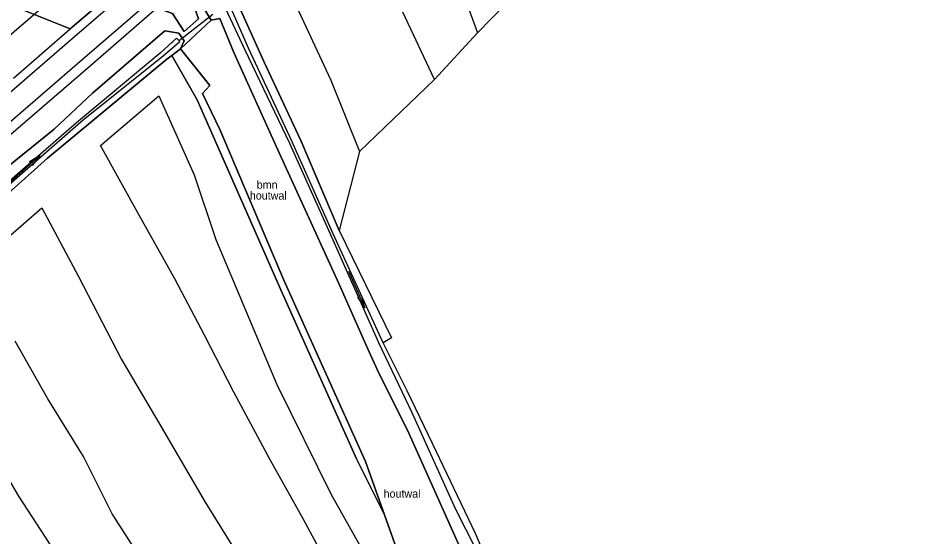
# Model space of a CAD drawing. Extents: x 154825 to 158680, y 370717 to 378075.
# Drawn here: x 156377.5 to 156491.8, y 376409.5 to 376474.3 of the extents above; entities that cross this region are included whole.
import ezdxf

# ---------------------------------------------------------------- set-up
doc = ezdxf.new("R2010")
doc.units = 0
for name, color, linetype in [('boomgroep(vs)', 7, 'Continuous'), ('cultuurscheiding', 7, 'Continuous'), ('deelstreep(1-1)', 7, 'Continuous'), ('duiker lijn', 7, 'Continuous'), ('hoogteverschillijn', 7, 'Continuous'), ('houtwal(vs)', 7, 'Continuous'), ('insteek sloot', 7, 'Continuous'), ('maaiveldlijn algemeen - gesloten verharding', 7, 'Continuous'), ('maaiveldlijn algemeen - open verharding', 7, 'Continuous'), ('Sloot bodem', 7, 'Continuous'), ('stroomrichting  watergangen', 7, 'Continuous'), ('talud(boven)', 7, 'Continuous'), ('talud(onder)', 7, 'Continuous'), ('vlak_Grasland', 7, 'Continuous'), ('vlak_Grazige_vegetatie', 7, 'Continuous'), ('vlak_Houtwal', 7, 'Continuous')]:
    doc.layers.add(name, color=color, linetype=linetype)

msp = doc.modelspace()

# ---------------------------------------------------------------- linework, layer by layer
at = {"layer": 'cultuurscheiding'}
for points in [[(156397.71, 376470.44), (156401.53, 376474)], [(156452.65, 376347.26), (156446.7, 376358.65), (156445.4, 376361.14), (156438.16, 376376.92), (156432.48, 376390.3), (156425.59, 376405.55), (156423.21, 376412.21), (156420.83, 376418.88)]]:
    msp.add_lwpolyline(points, dxfattribs=at)
at = {"layer": 'deelstreep(1-1)'}
for points in [[(156516.83, 376582.62), (156511, 376577.54), (156493.7, 376562.56), (156474.6, 376546.08), (156453.2, 376527.6), (156434.78, 376511.75), (156416.83, 376496.18), (156407.99, 376488.58), (156398.63, 376480.48), (156385.72, 376469.31), (156365.99, 376452.26), (156341.76, 376431.35), (156332.22, 376423.09), (156319.31, 376411.94), (156302.65, 376397.56), (156288.29, 376385.16), (156270.13, 376369.48), (156252.69, 376354.41), (156230.71, 376335.36), (156215.59, 376322.29), (156199.58, 376308.45), (156183.79, 376294.7), (156174.04, 376286.04)], [(156396.64, 376482.44), (156384.5, 376471.95), (156365.43, 376455.45), (156339.64, 376433.19), (156325.08, 376420.64), (156318.27, 376414.74), (156309.76, 376407.44), (156295.49, 376395.09), (156278.82, 376380.65), (156257.66, 376362.34), (156244, 376350.5), (156228.74, 376337.37), (156210.53, 376321.66), (156193.88, 376307.21), (156180.98, 376295.95), (156172.67, 376288.57)]]:
    msp.add_lwpolyline(points, dxfattribs=at)
at = {"layer": 'duiker lijn'}
for points in [[(156381.13, 376476.15), (156374.83, 376470.77)], [(156401.75, 376474.73), (156397.61, 376471.49)]]:
    msp.add_lwpolyline(points, dxfattribs=at)
at = {"layer": 'hoogteverschillijn'}
for points in [[(156430.99, 376482.94), (156434.81, 376472.42), (156441.98, 376479.81)], [(156411.65, 376476.95), (156416.51, 376466.53), (156420.08, 376457.59), (156429.44, 376466.61), (156425.47, 376475.01)], [(156418.27, 376401.97), (156413.05, 376411.71), (156408.9, 376419.06), (156404.37, 376427.51), (156400.72, 376434.67), (156397, 376441.68), (156392.62, 376449.57), (156387.71, 376458.36), (156395.02, 376464.55), (156399.43, 376454.71), (156402.15, 376446.59), (156406.21, 376436.92), (156409.74, 376428.48), (156416.52, 376414.76), (156421.96, 376405.11)], [(156371.57, 376442.92), (156380.41, 376450.57), (156384.97, 376441.97), (156390.35, 376431.63), (156395.02, 376423.71), (156400.82, 376413.77), (156406.72, 376404.24)], [(156393.38, 376405.8), (156389.17, 376412.33), (156385.61, 376419.48), (156381.16, 376426.69), (156377.09, 376433.91)], [(156372.83, 376422.46), (156377.47, 376414.52), (156382.98, 376406.08)]]:
    msp.add_lwpolyline(points, dxfattribs=at)
at = {"layer": 'insteek sloot'}
for points in [[(156401.53, 376474), (156400.68, 376475.44), (156400.56, 376476.25), (156404.61, 376480.44), (156405.83, 376481.53), (156416.42, 376490.67), (156424.67, 376497.23), (156425.57, 376496.46), (156426.08, 376495.82), (156425.87, 376495.16)], [(156415.57, 376486.13), (156408.41, 376479.61), (156404.91, 376475.98), (156408.18, 376468.77), (156412.75, 376458.97), (156417.53, 376447.73), (156424.07, 376434.34)], [(156401.53, 376474), (156402.63, 376474.21), (156404.38, 376469.98), (156409.85, 376457.89), (156417.48, 376441.12), (156420.88, 376433.49), (156422.33, 376430.29), (156426.23, 376422.42), (156433.21, 376406.88)], [(156397.71, 376470.44), (156398.16, 376471.43), (156397.51, 376472.38), (156395.76, 376472.68), (156386.74, 376464.91), (156381.96, 376460.41), (156372.31, 376452.63), (156362.32, 376443.31), (156361.14, 376441.74), (156361.34, 376441.19), (156362.08, 376440.64)], [(156362.08, 376440.64), (156363, 376440.98), (156374.21, 376450.62), (156381.12, 376456.78), (156396.01, 376469.15), (156396.64, 376469.62), (156397.71, 376470.44)]]:
    msp.add_lwpolyline(points, dxfattribs=at)
at = {"layer": 'maaiveldlijn algemeen - gesloten verharding'}
for points in [[(156383.95, 376472.95), (156396.18, 376483.38), (156405.38, 376491.44)], [(156237.38, 376339.6), (156253.19, 376353.26), (156271.08, 376368.68), (156289.08, 376384.27), (156303.76, 376396.95), (156320.09, 376411.16), (156332.73, 376421.99), (156342.37, 376430.35), (156366.77, 376451.41), (156386.5, 376468.35), (156394.77, 376475.56), (156398.53, 376478.84)], [(156376.85, 376466.78), (156383.95, 376472.95)]]:
    msp.add_lwpolyline(points, dxfattribs=at)
at = {"layer": 'maaiveldlijn algemeen - open verharding'}
for points in [[(156364.32, 376490.52), (156378.11, 376475.29), (156383.95, 376472.95)], [(156398.53, 376478.84), (156398.91, 376477.17), (156399.97, 376474.2), (156398.17, 376472.6), (156396.74, 376474.87), (156394.77, 376475.56)]]:
    msp.add_lwpolyline(points, dxfattribs=at)
at = {"layer": 'Sloot bodem'}
for points in [[(156436.48, 376405.4), (156434.58, 376409.86), (156429.21, 376421.11), (156426.03, 376427.69), (156423.04, 376433.69), (156416.76, 376447.38), (156411.65, 376458.81), (156406.23, 376470.52), (156403.75, 376476.15)], [(156403.28, 376475.55), (156405.75, 376470.3), (156411.34, 376458.66), (156416.4, 376447.3), (156422.43, 376433.73), (156426.61, 376425), (156432.08, 376412.91), (156435.99, 376405.22)], [(156397.63, 376471.34), (156397.22, 376471.79), (156395.22, 376469.92), (156384.72, 376461.21), (156373.14, 376451.17), (156365.95, 376444.97), (156361.92, 376441.45), (156362.33, 376441.17), (156366.29, 376444.83), (156373.33, 376450.92), (156385.59, 376461.59), (156395.56, 376469.56), (156397.63, 376471.34)]]:
    msp.add_lwpolyline(points, dxfattribs=at)
at = {"layer": 'stroomrichting  watergangen'}
for p, q in [((156376.46, 376453.76), (156380.17, 376457.1)), ((156380.15, 376457.1), (156378.81, 376456.26)), ((156380.17, 376457.1), (156379.2, 376455.86)), ((156418.71, 376442.64), (156420.75, 376438.08)), ((156420.75, 376438.08), (156419.87, 376439.39)), ((156420.76, 376438.1), (156420.37, 376439.63))]:
    msp.add_line(p, q, dxfattribs=at)
at = {"layer": 'talud(boven)'}
msp.add_lwpolyline([(156420.83, 376418.88), (156410.61, 376441.54), (156402.68, 376460.28), (156400.46, 376464.86), (156401.4, 376465.86), (156397.71, 376470.44)], dxfattribs=at)
at = {"layer": 'talud(onder)'}
msp.add_lwpolyline([(156396.64, 376469.62), (156399.82, 376464.08), (156410.25, 376440.3), (156419.69, 376419.2), (156423.21, 376412.21)], dxfattribs=at)
at = {"layer": 'vlak_Grasland'}
for points in [[(156498.8, 376534.69), (156491.35, 376527.99), (156483.75, 376520.44), (156476.1, 376513.3), (156463.92, 376501.56), (156456.32, 376494.05), (156449.89, 376487.84), (156441.98, 376479.81), (156434.81, 376472.42), (156429.44, 376466.61), (156420.08, 376457.59), (156417.53, 376447.73), (156412.75, 376458.97), (156408.18, 376468.77), (156404.91, 376475.98), (156408.41, 376479.61), (156415.57, 376486.13), (156425.87, 376495.16), (156429.84, 376498.71), (156430.29, 376499.02), (156444.62, 376511.66), (156458.94, 376524.45), (156474.27, 376537.24), (156478.66, 376540.59)], [(156374.21, 376450.62), (156381.12, 376456.78), (156396.01, 376469.15), (156396.64, 376469.62), (156399.82, 376464.08), (156410.25, 376440.3), (156419.69, 376419.2), (156423.21, 376412.21), (156425.59, 376405.55)]]:
    msp.add_lwpolyline(points, dxfattribs=at)
at = {"layer": 'vlak_Grazige_vegetatie'}
for points in [[(156366.77, 376451.41), (156386.5, 376468.35), (156394.77, 376475.56), (156396.74, 376474.87), (156398.17, 376472.6), (156399.97, 376474.2), (156398.91, 376477.17), (156398.53, 376478.84), (156399.36, 376479.56), (156408.72, 376487.7), (156417.69, 376495.41), (156435.44, 376510.68), (156453.82, 376526.69), (156471.48, 376541.88)], [(156461.65, 376540.91), (156443.64, 376525.47), (156424.27, 376508.77), (156405.06, 376491.77), (156405.38, 376491.44), (156396.18, 376483.38), (156383.95, 376472.95), (156378.11, 376475.29), (156364.32, 376490.52)], [(156404.91, 376475.98), (156408.18, 376468.77), (156412.75, 376458.97), (156417.53, 376447.73), (156424.07, 376434.34), (156423.04, 376433.69), (156416.76, 376447.38), (156411.65, 376458.81), (156406.23, 376470.52), (156403.75, 376476.15)], [(156400.68, 376475.44), (156401.53, 376474), (156397.71, 376470.44), (156398.16, 376471.43), (156397.51, 376472.38), (156395.76, 376472.68), (156386.74, 376464.91), (156381.96, 376460.41), (156372.31, 376452.63)], [(156433.21, 376406.88), (156426.23, 376422.42), (156422.33, 376430.29), (156420.88, 376433.49), (156417.48, 376441.12), (156409.85, 376457.89), (156404.38, 376469.98), (156402.63, 376474.21), (156401.53, 376474), (156400.68, 376475.44)], [(156403.28, 376475.55), (156405.75, 376470.3), (156411.34, 376458.66), (156416.4, 376447.3), (156422.43, 376433.73), (156426.61, 376425), (156432.08, 376412.91), (156435.99, 376405.22)]]:
    msp.add_lwpolyline(points, dxfattribs=at)
for points in [[(156397.51, 376472.38), (156398.16, 376471.43), (156397.71, 376470.44), (156396.64, 376469.62), (156396.01, 376469.15), (156381.12, 376456.78), (156374.21, 376450.62), (156363, 376440.98), (156362.08, 376440.64), (156361.34, 376441.19), (156361.14, 376441.74), (156362.32, 376443.31), (156372.31, 376452.63), (156381.96, 376460.41), (156386.74, 376464.91), (156395.76, 376472.68)], [(156361.92, 376441.45), (156362.33, 376441.17), (156366.29, 376444.83), (156373.33, 376450.92), (156385.59, 376461.59), (156395.56, 376469.56), (156397.63, 376471.34), (156397.22, 376471.79), (156395.22, 376469.92), (156384.72, 376461.21), (156373.14, 376451.17), (156365.95, 376444.97)], [(156420.83, 376418.88), (156423.21, 376412.21), (156419.69, 376419.2), (156410.25, 376440.3), (156399.82, 376464.08), (156396.64, 376469.62), (156397.71, 376470.44), (156401.4, 376465.86), (156400.46, 376464.86), (156402.68, 376460.28), (156410.61, 376441.54)]]:
    msp.add_lwpolyline(points, close=True, dxfattribs=at)
at = {"layer": 'vlak_Houtwal'}
msp.add_lwpolyline([(156425.59, 376405.55), (156423.21, 376412.21), (156420.83, 376418.88), (156410.61, 376441.54), (156402.68, 376460.28), (156400.46, 376464.86), (156401.4, 376465.86), (156397.71, 376470.44), (156401.53, 376474), (156402.63, 376474.21), (156404.38, 376469.98), (156409.85, 376457.89), (156417.48, 376441.12), (156420.88, 376433.49), (156422.33, 376430.29), (156426.23, 376422.42), (156433.21, 376406.88)], dxfattribs=at)

# ---------------------------------------------------------------- texts
at = {"layer": 'boomgroep(vs)'}
msp.add_text('bmn', height=1, dxfattribs=at).set_placement((156407.24, 376452.96))
at = {"layer": 'houtwal(vs)'}
for p in [(156406.38, 376451.6), (156423.09, 376414.35)]:
    msp.add_text('houtwal', height=1, dxfattribs=at).set_placement(p)

doc.saveas('drawing.dxf')
